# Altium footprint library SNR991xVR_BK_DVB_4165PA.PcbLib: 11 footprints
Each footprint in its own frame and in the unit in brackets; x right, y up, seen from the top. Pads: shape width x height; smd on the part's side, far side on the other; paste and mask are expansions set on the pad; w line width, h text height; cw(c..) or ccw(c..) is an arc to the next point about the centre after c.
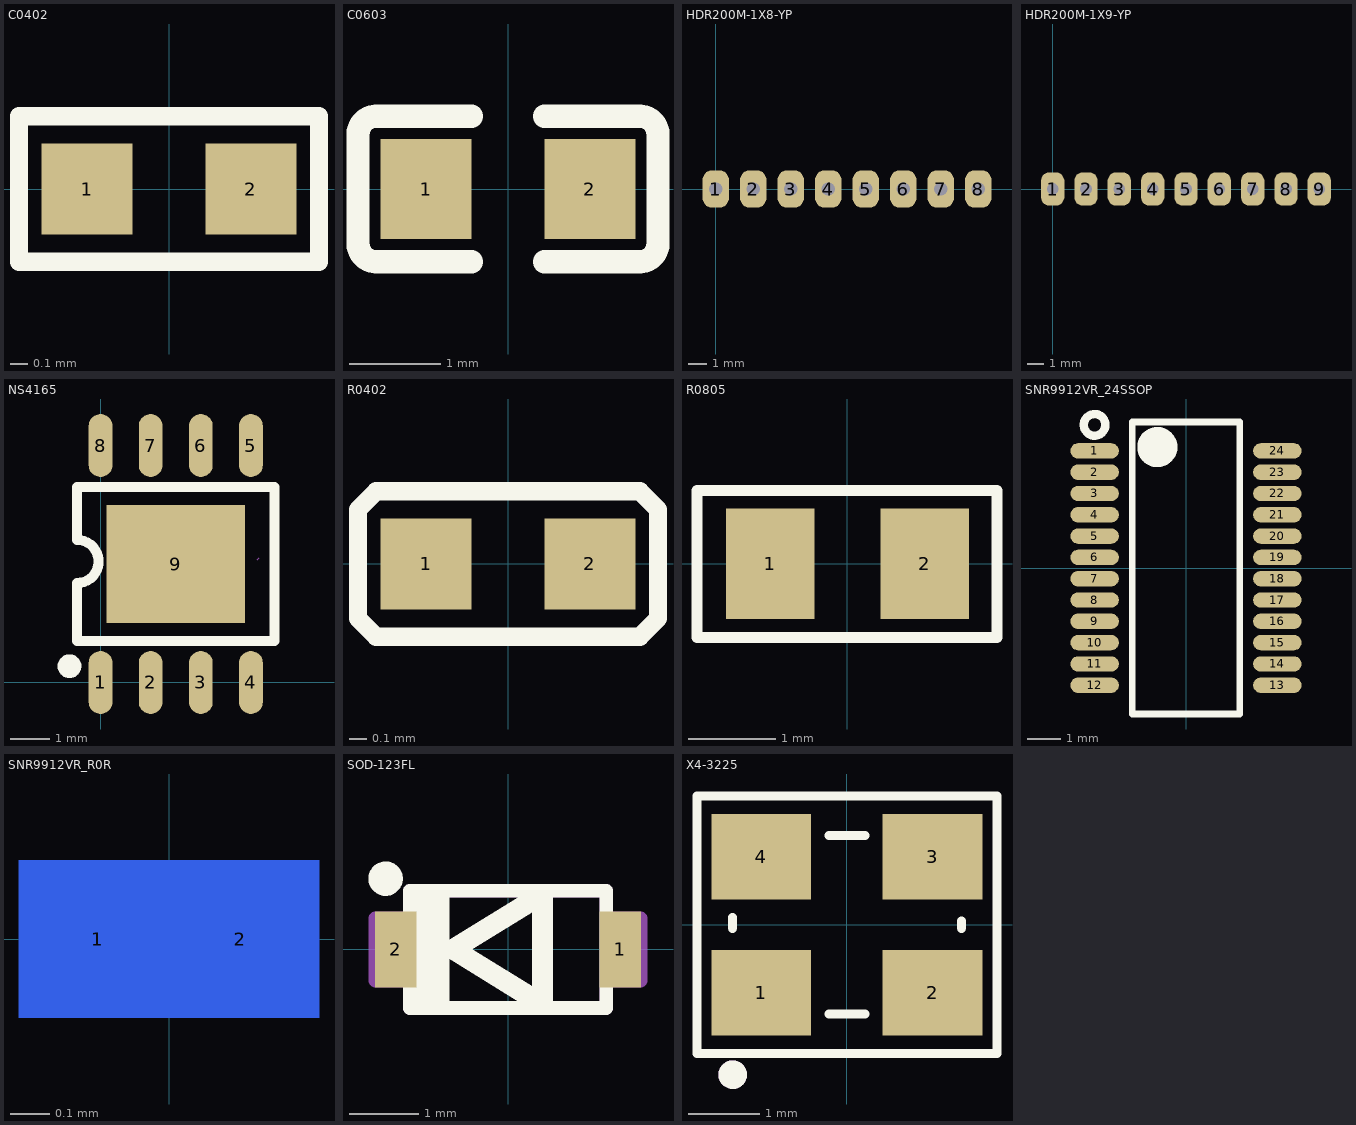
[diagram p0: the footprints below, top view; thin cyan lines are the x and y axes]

## C0402 [mil] "C0402"
pads (2):
  rect 20x20 smd: 1(-17.99,0) 2(17.99,0)
Top Overlay:
  lines w4.02: -32.99,-15.98 -32.99,15.98 32.99,15.98 32.99,-15.98 29.02,-15.98 -32.99,-15.98
Mechanical 27:
  text "2012-0607" at -33.31,21.81 h7.87
Mechanical 46:
  text "1" at -27.99,0 h25
  text "2" at 7.99,0 h25

## C0603 [mm]
pads (2):
  rect 1x1.1 smd: 1(-0.9,0) 2(0.9,0)
Top Overlay:
  lines w0.254: -0.4,-0.8 -1.4,-0.8 -1.45,-0.8 cw(c-1.45,-0.6) -1.65,-0.6 -1.65,0.6 cw(c-1.45,0.6) -1.45,0.8 -1.4,0.8 -0.4,0.8 ; 0.4,-0.8 1.4,-0.8 1.45,-0.8 ccw(c1.45,-0.6) 1.65,-0.6 1.65,0.6 ccw(c1.45,0.6) 1.45,0.8 1.4,0.8 0.4,0.8

## HDR200M-1X8-YP [mm] "HDR200M-1X8-YP"
pads (8):
  rrect71% 1.4x2 / inner round 1.524 / far side rrect71% 1.4x2.6 hole 0.7: 1(0,0) 2(2,0) 3(4,0) 4(6,0) 5(8,0) 6(10,0) 7(12,0) 8(14,0)
Mechanical 46:
  text "8" at 13.84,0 h0.4
  text "4" at 5.84,0 h0.4
  text "7" at 11.84,0 h0.4
  text "1" at -0.16,0 h0.4
  text "6" at 9.84,0 h0.4
  text "5" at 7.84,0 h0.4
  text "2" at 1.84,0 h0.4
  text "3" at 3.84,0 h0.4

## HDR200M-1X9-YP [mm] "HDR200M-1X9-YP"
pads (9):
  rrect71% 1.4x2 / inner round 1.524 / far side rrect71% 1.4x2.6 hole 0.7: 1(0,0) 2(2,0) 3(4,0) 4(6,0) 5(8,0) 6(10,0) 7(12,0) 8(14,0) 9(16,0)
Mechanical 46:
  text "8" at 13.84,0 h0.4
  text "7" at 11.84,0 h0.4
  text "2" at 1.84,0 h0.4
  text "3" at 3.84,0 h0.4
  text "9" at 15.84,0 h0.4
  text "4" at 5.84,0 h0.4
  text "5" at 7.84,0 h0.4
  text "1" at -0.16,0 h0.4
  text "6" at 9.84,0 h0.4

## NS4165 [mm]
pads (9):
  oval 0.6x1.598 smd: 1(0,0) 2(1.27,0) 3(2.54,0) 4(3.81,0) 5(3.81,6) 6(2.54,6) 7(1.27,6) 8(0,6)
  rect 3.5x3 smd: 9(1.905,3)
Top Overlay:
  lines w0.254: -0.595,1.05 -0.595,2.517 ccw(c-0.595,3.063) -0.595,3.61 -0.595,4.95 4.405,4.95 4.405,1.05 -0.595,1.05
  lines w0.3: -0.787,0.562 ccw(c-0.786,0.412) -0.785,0.562
Mechanical 15:
  lines w0.003: 3.975,3.102 4.026,3.152

## R0402 [mil] "R0402"
pads (2):
  rect 20x20 smd: 1(-17.99,0) 2(17.99,0)
Top Overlay:
  lines w4.02: -32.99,-12.01 -29.02,-15.98 29.02,-15.98 32.99,-12.01 32.99,12.01 29.02,15.98 -29.02,15.98 -32.99,12.01 -32.99,-12.01
Mechanical 27:
  text "2012-0607" at -33.31,21.81 h7.87
Mechanical 46:
  text "2" at 17.99,10 h25
  text "1" at -17.99,10 h25

## R0805 [mil]
pads (2):
  rect 40x50 smd: 1(-35,0) 2(35,0)
Top Overlay:
  lines w5: -68.03,-33.35 67.64,-33.35 67.64,33.03 -68.03,33.03 -68.03,-33.35

## SNR9912VR_24SSOP [mil]
pads (24):
  oval 57x18 smd: 1(-107.28,137.5) 2(-107.28,112.5) 3(-107.28,87.5) 4(-107.28,62.5) 5(-107.28,37.5) 6(-107.28,12.5) 7(-107.28,-12.5) 8(-107.28,-37.5) 9(-107.28,-62.5) 10(-107.28,-87.5) 11(-107.28,-112.5) 12(-107.28,-137.5) 13(107.28,-137.5) 14(107.28,-112.5) 15(107.28,-87.5) 16(107.28,-62.5) 17(107.28,-37.5) 18(107.28,-12.5) 19(107.28,12.5) 20(107.28,37.5) 21(107.28,62.5) 22(107.28,87.5) 23(107.28,112.5) 24(107.28,137.5)
Top Overlay:
  circle w9.84: c-107.28,168.01 r12.74
  circle w23.62: c-33.62,141.89 r11.81
  lines w7.87: -62.99,-171.26 -62.99,171.26 62.99,171.26 62.99,-171.26 -62.99,-171.26

## SNR9912VR_R0R [mm]
pads (2):
  rrect0% 0.4x0.4 smd far side: 1(-0.18,0) 2(0.18,0)

## SOD-123FL [mm]
pads (2):
  rect 0.6x1.1 smd: 1(1.625,0) 2(-1.625,0)
Top Overlay:
  circle w0.25: c-1.775,1.025 r0.125
  lines w0.2: -1.425,-0.85 -1.425,0.85 1.425,0.85 1.425,-0.85 -1.425,-0.85
  lines w0.3: -1.2,-0.8 -1.2,0.8 -1,0.8 -1,-0.8 ; -0.8,0 0.5,0.8 0.5,-0.8 -0.8,0
Mechanical 16:
  lines w0.2: -1.325,0.85 -1.325,-0.85 -1.225,-0.85 -1.225,0.85 -1.125,0.85 ; -1.125,-0.85 -1.025,-0.85 ; -1.025,0.85 -0.925,0.85 ; -1.925,-0.45 -1.525,-0.45 -1.525,0.45 -1.925,0.45 -1.925,-0.45 ; -1.425,-0.85 1.425,-0.85 1.425,0.85 -1.425,0.85 -1.425,-0.85 ; 1.525,-0.45 1.925,-0.45 1.925,0.45 1.525,0.45 1.525,-0.45
Mechanical 19:
  text "D1" at 0,-0.52 h0.2

## X4-3225 [mm]
pads (4):
  rect 1.399x1.199 smd: 1(-1.2,-0.95) 2(1.2,-0.95) 3(1.2,0.95) 4(-1.2,0.95)
Top Overlay:
  circle w0.2: c-1.6,-2.1 r0.1
  lines w0.127: -1.6,-0.05 -1.6,0.1 ; -0.25,-1.25 0.25,-1.25 ; -0.25,1.25 0.25,1.25 ; 1.6,-0.05 1.6,0.05 ; -2.1,-1.8 2.1,-1.8 2.1,1.8 -2.1,1.8 -2.1,-1.8
Mechanical 16:
  circle w0.2: c-1.6,-2.1 r0.1
Mechanical 19:
  text "Y1" at -0.9,-0.4 h0.46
